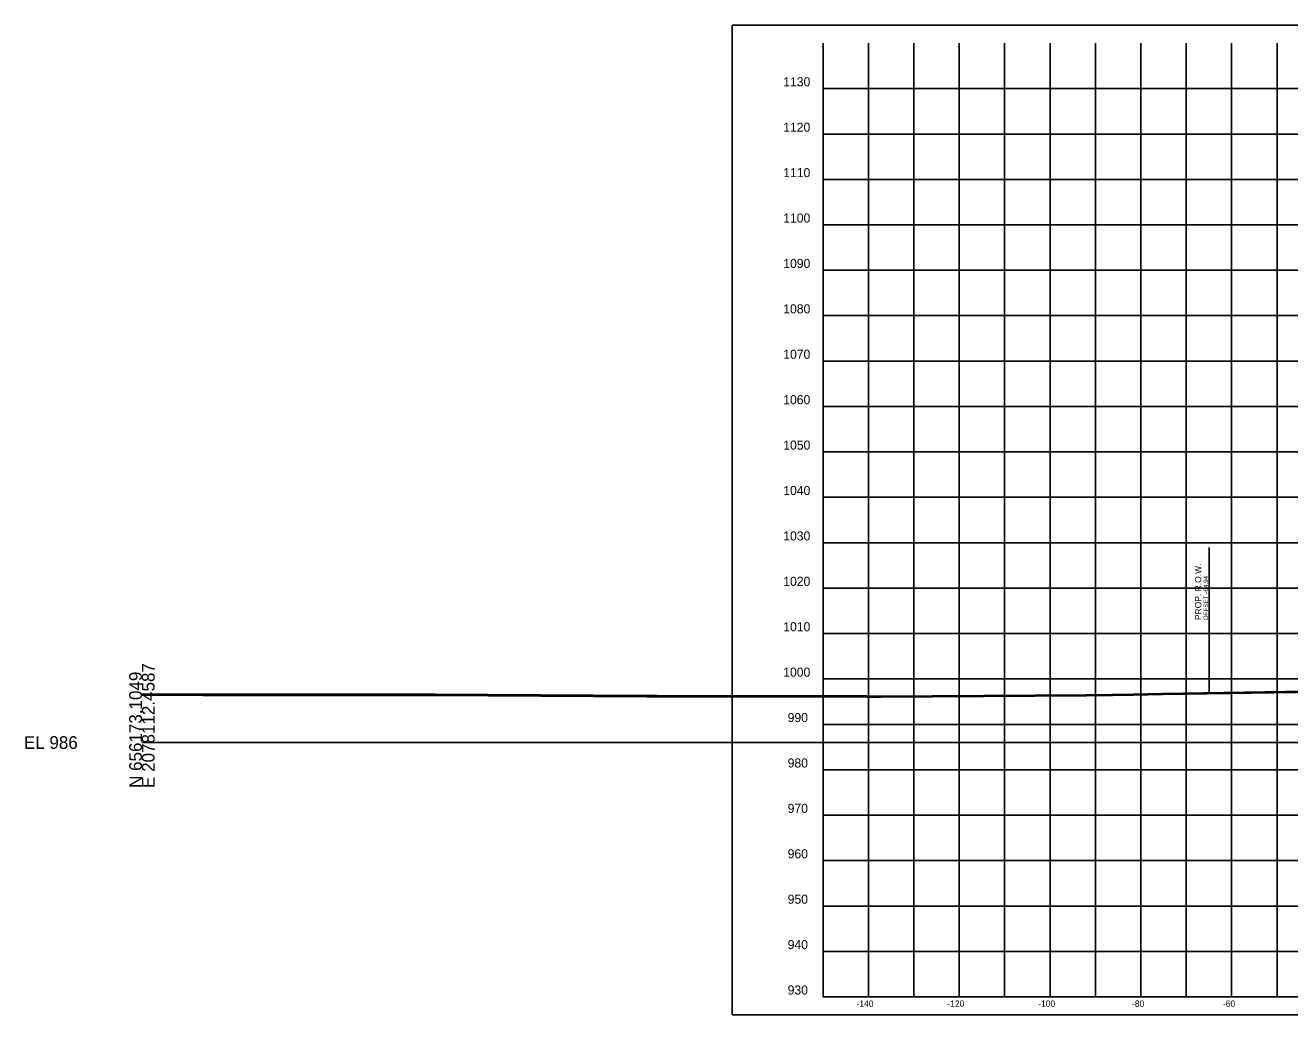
# Model space of a CAD drawing. Extents: x 5868 to 6683, y 2883 to 19120.
# Drawn here: x 5868.1 to 6146.6, y 12385.1 to 12603 of the extents above; entities that cross this region are included whole.
import ezdxf

# ---------------------------------------------------------------- set-up
doc = ezdxf.new("R2010")
doc.units = 0
for name, color, linetype in [('DESIGN - ROW - Right-of-Way and Easement Labels', 7, 'Continuous'), ('DESIGN - ROW - Right-of-Way Linework', 7, 'Continuous'), ('DESIGN - SHEET - Corner Text', 7, 'Continuous'), ('DESIGN - SHEET - Light Grid', 7, 'Continuous'), ('DESIGN - SHEET - Linework', 7, 'Continuous'), ('DESIGN - SHEET - Plot Shape', 7, 'Continuous'), ('SURVEY - GROUND - Bottom of Topsoil Layer', 7, 'Continuous'), ('SURVEY - GROUND - Top of Ground', 7, 'Continuous')]:
    doc.layers.add(name, color=color, linetype=linetype)

msp = doc.modelspace()

# ---------------------------------------------------------------- linework, layer by layer
at = {"layer": 'DESIGN - ROW - Right-of-Way Linework'}
msp.add_line((6128.84, 12456.02), (6128.84, 12488.02), dxfattribs=at)
at = {"layer": 'DESIGN - SHEET - Light Grid'}
msp.add_line((5893.78, 12445.07), (6193.78, 12445.07), dxfattribs=at)
at = {"layer": 'DESIGN - SHEET - Linework'}
for p, q in [((6053.78, 12389.07), (6053.78, 12599.07)), ((6063.78, 12389.07), (6063.78, 12599.07)), ((6073.78, 12389.07), (6073.78, 12599.07)), ((6083.78, 12389.07), (6083.78, 12599.07)), ((6093.78, 12389.07), (6093.78, 12599.07)), ((6103.78, 12389.07), (6103.78, 12599.07)), ((6113.78, 12389.07), (6113.78, 12599.07)), ((6123.78, 12389.07), (6123.78, 12599.07)), ((6133.78, 12389.07), (6133.78, 12599.07)), ((6143.78, 12389.07), (6143.78, 12599.07)), ((6043.78, 12589.07), (6343.78, 12589.07)), ((6043.78, 12579.07), (6343.78, 12579.07)), ((6043.78, 12569.07), (6343.78, 12569.07)), ((6043.78, 12559.07), (6343.78, 12559.07)), ((6043.78, 12549.07), (6343.78, 12549.07)), ((6043.78, 12539.07), (6343.78, 12539.07)), ((6043.78, 12529.07), (6343.78, 12529.07)), ((6043.78, 12519.07), (6343.78, 12519.07)), ((6043.78, 12509.07), (6343.78, 12509.07)), ((6043.78, 12499.07), (6343.78, 12499.07)), ((6043.78, 12489.07), (6343.78, 12489.07)), ((6043.78, 12479.07), (6343.78, 12479.07)), ((6043.78, 12469.07), (6343.78, 12469.07)), ((6043.78, 12459.07), (6343.78, 12459.07)), ((6043.78, 12449.07), (6343.78, 12449.07)), ((6043.78, 12439.07), (6343.78, 12439.07)), ((6043.78, 12429.07), (6343.78, 12429.07)), ((6043.78, 12419.07), (6343.78, 12419.07)), ((6043.78, 12409.07), (6343.78, 12409.07)), ((6043.78, 12399.07), (6343.78, 12399.07))]:
    msp.add_line(p, q, dxfattribs=at)
msp.add_lwpolyline([(6043.78, 12599.07), (6043.78, 12389.07), (6343.78, 12389.07), (6343.78, 12599.07)], dxfattribs=at)
at = {"layer": 'DESIGN - SHEET - Plot Shape'}
msp.add_lwpolyline([(6023.78, 12603.01), (6363.78, 12603.01), (6363.78, 12385.13), (6023.78, 12385.13)], close=True, dxfattribs=at)
at = {"layer": 'SURVEY - GROUND - Bottom of Topsoil Layer'}
for p, q in [((6118.57, 12455.61), (6154.7, 12456.17)), ((5893.78, 12455.51), (5907.21, 12455.46)), ((5907.21, 12455.46), (5945.54, 12455.45)), ((5945.54, 12455.45), (5957, 12455.45)), ((5957, 12455.45), (5958.39, 12455.45)), ((5958.39, 12455.45), (6004.9, 12455.16)), ((6004.9, 12455.16), (6007.22, 12455.16)), ((6007.22, 12455.16), (6053.42, 12455.07)), ((6053.42, 12455.07), (6056.58, 12455.06)), ((6056.58, 12455.06), (6101.74, 12455.34)), ((6101.74, 12455.34), (6107.53, 12455.4)), ((6107.53, 12455.4), (6112.1, 12455.49)), ((6112.1, 12455.49), (6118.57, 12455.61))]:
    msp.add_line(p, q, dxfattribs=at)
at = {"layer": 'SURVEY - GROUND - Top of Ground'}
msp.add_lwpolyline([(5893.78, 12455.76), (5907.21, 12455.71), (5945.54, 12455.7), (5957, 12455.7), (5958.39, 12455.7), (6004.9, 12455.41), (6007.22, 12455.41), (6053.42, 12455.32), (6056.58, 12455.31), (6101.74, 12455.59), (6107.53, 12455.65), (6112.1, 12455.74), (6118.57, 12455.86), (6154.7, 12456.42)], dxfattribs=at)

# ---------------------------------------------------------------- texts
at = {"layer": 'DESIGN - ROW - Right-of-Way and Easement Labels'}
for s, height, p in [('PROP. R.O.W.', 1.4, (6127.09, 12472.02)), ('OFFSET -64.94', 1, (6128.59, 12472.02))]:
    msp.add_text(s, height=height, rotation=90, dxfattribs=at).set_placement(p)
at = {"layer": 'DESIGN - SHEET - Corner Text'}
for s, height, p in [('1130', 2, (6035.03, 12589.57)), ('1120', 2, (6035.03, 12579.57)), ('1110', 2, (6035.03, 12569.57)), ('1100', 2, (6035.03, 12559.57)), ('1090', 2, (6035.03, 12549.57)), ('1080', 2, (6035.03, 12539.57)), ('1070', 2, (6035.03, 12529.57)), ('1060', 2, (6035.03, 12519.57)), ('1050', 2, (6035.03, 12509.57)), ('1040', 2, (6035.03, 12499.57)), ('1030', 2, (6035.03, 12489.57)), ('1020', 2, (6035.03, 12479.57)), ('1010', 2, (6035.03, 12469.57)), ('1000', 2, (6035.03, 12459.57)), ('990', 2, (6036, 12449.57)), ('980', 2, (6036, 12439.57)), ('970', 2, (6036, 12429.57)), ('960', 2, (6036, 12419.57)), ('950', 2, (6036, 12409.57)), ('940', 2, (6036, 12399.57)), ('930', 2, (6036, 12389.57)), ('-140', 1.4, (6051.16, 12386.87)), ('-120', 1.4, (6071.16, 12386.87)), ('-100', 1.4, (6091.16, 12386.87)), ('-80', 1.4, (6111.84, 12386.87)), ('-60', 1.4, (6131.84, 12386.87))]:
    msp.add_text(s, height=height, dxfattribs=at).set_placement(p)
at = {"layer": 'DESIGN - SHEET - Light Grid'}
for s, p in [('E 2078112.4587', (5896.58, 12435.07)), ('N 656173.1049', (5893.78, 12435.07))]:
    msp.add_text(s, height=2.8, rotation=90, dxfattribs=at).set_placement(p)
msp.add_text('EL 986', height=2.8, dxfattribs=at).set_placement((5867.78, 12443.67))

doc.saveas('drawing.dxf')
